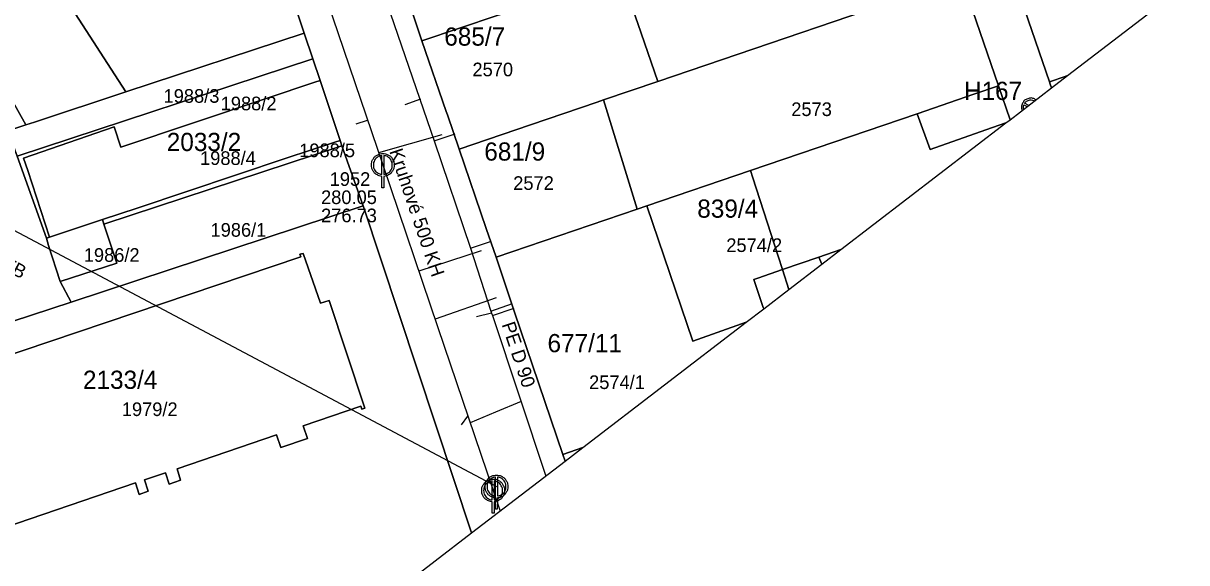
# Model space of a CAD drawing. Extents: x -570698 to -570232, y -1086952 to -1086596.
# Drawn here: x -570363.7 to -570235.9, y -1086825.7 to -1086766.4 of the extents above; entities that cross this region are included whole.
import ezdxf

# ---------------------------------------------------------------- set-up
doc = ezdxf.new("R2010")
doc.units = 0
for name, color, linetype in [('Adresní místo-text', 7, 'Continuous'), ('Default', 7, 'Continuous'), ('Hydrant', 7, 'Continuous'), ('Kanalizační přípojka', 7, 'Continuous'), ('Kanalizační stoka', 7, 'Continuous'), ('Kanalizační šachta', 7, 'Continuous'), ('Označení hydrantu', 7, 'Continuous'), ('Parcela-polygon', 7, 'Continuous'), ('Parcela-text', 7, 'Continuous'), ('Popis kmenové stoky', 7, 'Continuous'), ('Popis šachty', 7, 'Continuous'), ('Vodovodní přípojka', 7, 'Continuous'), ('Vodovodní řad', 7, 'Continuous'), ('Řad vodovodní popis', 7, 'Continuous')]:
    doc.layers.add(name, color=color, linetype=linetype)

msp = doc.modelspace()

# ---------------------------------------------------------------- linework, layer by layer
at = {"layer": 'Default'}
for points in [[(-570324.32, -1086783.21), (-570324.58, -1086783.19), (-570324.84, -1086783.04), (-570325.14, -1086782.88), (-570325.31, -1086782.58), (-570325.47, -1086782.28), (-570325.47, -1086781.96), (-570325.47, -1086781.63), (-570325.3, -1086781.33), (-570325.13, -1086781.03), (-570324.84, -1086780.87), (-570324.54, -1086780.71), (-570324.22, -1086780.71), (-570323.91, -1086780.71), (-570323.61, -1086780.87), (-570323.31, -1086781.03), (-570323.14, -1086781.33), (-570322.97, -1086781.63), (-570322.97, -1086781.96), (-570322.97, -1086782.28), (-570323.13, -1086782.58), (-570323.3, -1086782.88), (-570323.6, -1086783.04), (-570323.86, -1086783.19), (-570324.12, -1086783.21)], [(-570324.32, -1086780.92), (-570324.52, -1086780.94), (-570324.74, -1086781.05), (-570324.98, -1086781.19), (-570325.12, -1086781.44), (-570325.26, -1086781.69), (-570325.26, -1086781.96), (-570325.26, -1086782.23), (-570325.13, -1086782.48), (-570324.99, -1086782.72), (-570324.74, -1086782.86), (-570324.53, -1086782.98), (-570324.32, -1086783)], [(-570324.12, -1086783), (-570323.91, -1086782.98), (-570323.7, -1086782.86), (-570323.45, -1086782.72), (-570323.31, -1086782.48), (-570323.18, -1086782.23), (-570323.18, -1086781.96), (-570323.18, -1086781.69), (-570323.32, -1086781.44), (-570323.46, -1086781.19), (-570323.71, -1086781.05), (-570323.92, -1086780.94), (-570324.12, -1086780.92)], [(-570312.2, -1086819), (-570312.46, -1086818.98), (-570312.72, -1086818.83), (-570313.02, -1086818.67), (-570313.19, -1086818.37), (-570313.35, -1086818.07), (-570313.35, -1086817.75), (-570313.35, -1086817.42), (-570313.18, -1086817.12), (-570313.01, -1086816.82), (-570312.72, -1086816.66), (-570312.42, -1086816.5), (-570312.1, -1086816.5), (-570311.79, -1086816.5), (-570311.49, -1086816.66), (-570311.19, -1086816.82), (-570311.02, -1086817.12), (-570310.85, -1086817.42), (-570310.85, -1086817.75), (-570310.85, -1086818.07), (-570311.01, -1086818.37), (-570311.18, -1086818.67), (-570311.48, -1086818.83), (-570311.74, -1086818.98), (-570312, -1086819)], [(-570311.84, -1086818.57), (-570312.1, -1086818.55), (-570312.36, -1086818.4), (-570312.65, -1086818.24), (-570312.82, -1086817.94), (-570312.98, -1086817.64), (-570312.98, -1086817.32), (-570312.98, -1086816.99), (-570312.81, -1086816.69), (-570312.64, -1086816.39), (-570312.34, -1086816.23), (-570312.04, -1086816.07), (-570311.72, -1086816.07), (-570311.41, -1086816.07), (-570311.11, -1086816.23), (-570310.81, -1086816.4), (-570310.65, -1086816.7), (-570310.48, -1086817), (-570310.48, -1086817.33), (-570310.48, -1086817.65), (-570310.65, -1086817.95), (-570310.81, -1086818.24), (-570311.11, -1086818.41), (-570311.37, -1086818.55), (-570311.63, -1086818.57)], [(-570311.83, -1086816.28), (-570312.03, -1086816.3), (-570312.24, -1086816.41), (-570312.49, -1086816.55), (-570312.63, -1086816.8), (-570312.77, -1086817.05), (-570312.77, -1086817.32), (-570312.77, -1086817.59), (-570312.64, -1086817.83), (-570312.5, -1086818.08), (-570312.25, -1086818.22), (-570312.04, -1086818.34), (-570311.84, -1086818.36)], [(-570311.63, -1086818.36), (-570311.43, -1086818.34), (-570311.21, -1086818.22), (-570310.96, -1086818.09), (-570310.83, -1086817.84), (-570310.69, -1086817.6), (-570310.69, -1086817.33), (-570310.69, -1086817.05), (-570310.82, -1086816.8), (-570310.96, -1086816.55), (-570311.21, -1086816.42), (-570311.42, -1086816.3), (-570311.62, -1086816.28)], [(-570312.2, -1086816.71), (-570312.4, -1086816.73), (-570312.62, -1086816.84), (-570312.86, -1086816.98), (-570313, -1086817.23), (-570313.14, -1086817.48), (-570313.14, -1086817.75), (-570313.14, -1086818.02), (-570313.01, -1086818.27), (-570312.87, -1086818.51), (-570312.62, -1086818.65), (-570312.41, -1086818.77), (-570312.2, -1086818.79)], [(-570312, -1086818.79), (-570311.79, -1086818.77), (-570311.58, -1086818.65), (-570311.33, -1086818.51), (-570311.19, -1086818.27), (-570311.06, -1086818.02), (-570311.06, -1086817.75), (-570311.06, -1086817.48), (-570311.2, -1086817.23), (-570311.34, -1086816.98), (-570311.59, -1086816.84), (-570311.8, -1086816.73), (-570312, -1086816.71)]]:
    msp.add_open_spline(points, degree=3, dxfattribs=at)
at = {"layer": 'Hydrant'}
for p, q in [((-570253.77, -1086775.35), (-570253.39, -1086775.53)), ((-570253.23, -1086775.41), (-570253.69, -1086775.18)), ((-570253.39, -1086775.53), (-570253.23, -1086775.41)), ((-570252.59, -1086774.92), (-570252.43, -1086774.79)), ((-570253.94, -1086775.96), (-570253.78, -1086775.83))]:
    msp.add_line(p, q, dxfattribs=at)
for points, degree in [([(-570252.43, -1086774.79), (-570252.49, -1086774.75), (-570252.57, -1086774.72), (-570252.94, -1086774.54), (-570253.33, -1086774.68), (-570253.72, -1086774.81), (-570253.9, -1086775.18), (-570254.08, -1086775.56), (-570253.95, -1086775.95), (-570253.94, -1086775.95), (-570253.94, -1086775.96)], 3), ([(-570253.78, -1086775.83), (-570253.85, -1086775.59), (-570253.77, -1086775.35)], 2), ([(-570253.69, -1086775.18), (-570253.54, -1086774.95), (-570253.27, -1086774.85), (-570252.95, -1086774.74), (-570252.64, -1086774.89), (-570252.62, -1086774.9), (-570252.59, -1086774.92)], 3)]:
    msp.add_open_spline(points, degree=degree, dxfattribs=at)
at = {"layer": 'Kanalizační přípojka'}
for points in [[(-570327.16, -1086777.45), (-570325.89, -1086777.04)], [(-570317.74, -1086778.63), (-570324.68, -1086780.62)], [(-570313.43, -1086791.39), (-570320.26, -1086793.65)], [(-570311.78, -1086796.56), (-570318.48, -1086798.9)], [(-570309.02, -1086807.97), (-570311.82, -1086809.14), (-570314.62, -1086810.32)], [(-570315.57, -1086810.52), (-570314.86, -1086809.6)]]:
    msp.add_lwpolyline(points, dxfattribs=at)
at = {"layer": 'Kanalizační stoka'}
msp.add_line((-570387.02, -1086777.34), (-570311.73, -1086817.32), dxfattribs=at)
for points in [[(-570339.23, -1086738.28), (-570338.99, -1086738.49), (-570331.6, -1086760.23), (-570324.22, -1086781.96)], [(-570324.22, -1086781.96), (-570318.16, -1086799.85), (-570312.1, -1086817.75)], [(-570312.1, -1086817.75), (-570311.33, -1086820.02)]]:
    msp.add_lwpolyline(points, dxfattribs=at)
at = {"layer": 'Kanalizační šachta'}
for points in [[(-570324.32, -1086783), (-570324.32, -1086780.92)], [(-570324.12, -1086780.92), (-570324.12, -1086783)], [(-570324.12, -1086783.21), (-570324.12, -1086784.46), (-570324.32, -1086784.46), (-570324.32, -1086783.21)], [(-570311.84, -1086818.36), (-570311.83, -1086816.28)], [(-570311.62, -1086816.28), (-570311.63, -1086818.36)], [(-570312.2, -1086818.79), (-570312.2, -1086816.71)], [(-570312, -1086816.71), (-570312, -1086818.79)], [(-570312, -1086819), (-570312, -1086820.25), (-570312.2, -1086820.25), (-570312.2, -1086819)], [(-570311.63, -1086818.57), (-570311.64, -1086819.82), (-570311.84, -1086819.82), (-570311.84, -1086818.57)]]:
    msp.add_lwpolyline(points, dxfattribs=at)
at = {"layer": 'Parcela-polygon'}
for p, q in [((-570248.97, -1086772.14), (-570235.86, -1086762.07)), ((-570250.72, -1086773.48), (-570248.97, -1086772.14)), ((-570255.28, -1086776.98), (-570250.72, -1086773.48)), ((-570273.89, -1086791.27), (-570255.74, -1086777.34)), ((-570255.74, -1086777.34), (-570255.28, -1086776.98)), ((-570275.98, -1086792.88), (-570273.89, -1086791.27)), ((-570279.58, -1086795.64), (-570275.98, -1086792.88)), ((-570282.35, -1086797.77), (-570279.58, -1086795.64)), ((-570284.29, -1086799.25), (-570282.35, -1086797.77)), ((-570302.24, -1086813.03), (-570284.29, -1086799.25)), ((-570304.18, -1086814.52), (-570302.24, -1086813.03)), ((-570314.47, -1086822.42), (-570304.18, -1086814.52)), ((-570427.79, -1086909.43), (-570314.47, -1086822.42))]:
    msp.add_line(p, q, dxfattribs=at)
for points in [[(-570250.72, -1086773.48), (-570250.86, -1086773.06), (-570250.95, -1086772.82), (-570253.65, -1086764.94), (-570267.22, -1086725.38), (-570267.25, -1086723.7), (-570266.64, -1086718.69), (-570284.42, -1086711.51), (-570289.55, -1086724.3), (-570275.18, -1086729.09), (-570271.35, -1086730.46), (-570268.66, -1086737.98), (-570264.62, -1086749.76), (-570260.63, -1086761.38), (-570256.55, -1086773.27), (-570255.28, -1086776.98)], [(-570338.47, -1086750.66), (-570332.86, -1086767.46), (-570331.91, -1086770.3), (-570331.11, -1086772.68), (-570328.92, -1086779.26), (-570328.72, -1086779.86), (-570326.4, -1086786.46), (-570314.47, -1086822.42)], [(-570304.18, -1086814.52), (-570304.43, -1086813.78), (-570309.74, -1086798.14), (-570311.76, -1086792.1), (-570312.86, -1086788.94), (-570315.83, -1086780.22), (-570317.13, -1086776.46), (-570317.27, -1086776.07), (-570319.93, -1086768.31), (-570322.84, -1086759.63)], [(-570235.86, -1086762.07), (-570240.33, -1086763.5), (-570241.14, -1086760.94), (-570252.23, -1086764.49), (-570253.65, -1086764.94), (-570250.95, -1086772.82), (-570249.24, -1086772.23), (-570248.97, -1086772.14)], [(-570248.97, -1086772.14), (-570249.24, -1086772.23), (-570250.95, -1086772.82), (-570250.86, -1086773.06), (-570250.72, -1086773.48)], [(-570255.28, -1086776.98), (-570256.55, -1086773.27), (-570259.26, -1086774.19), (-570265.5, -1086776.32), (-570264.05, -1086780.26), (-570257.95, -1086778.09), (-570255.74, -1086777.34)], [(-570255.74, -1086777.34), (-570257.95, -1086778.09), (-570264.05, -1086780.26), (-570265.5, -1086776.32), (-570283.82, -1086782.57), (-570283.56, -1086783.38), (-570280.76, -1086792), (-570280.29, -1086793.46), (-570276.29, -1086792.09), (-570273.89, -1086791.27)], [(-570282.35, -1086797.77), (-570282.4, -1086797.62), (-570283.46, -1086794.55), (-570283.02, -1086794.4), (-570280.29, -1086793.46), (-570280.76, -1086792), (-570283.56, -1086783.38), (-570283.82, -1086782.57), (-570295.2, -1086786.45), (-570290.13, -1086801.35), (-570284.29, -1086799.25)], [(-570314.47, -1086822.42), (-570326.4, -1086786.46), (-570358.49, -1086797.03), (-570369.36, -1086800.59), (-570374.8, -1086803.82), (-570380.97, -1086807.48), (-570374.82, -1086826.12), (-570380.47, -1086828.04), (-570398.24, -1086834.1), (-570397.51, -1086836.02), (-570406.58, -1086839.09), (-570441.99, -1086865.7), (-570438.81, -1086873.31), (-570432.93, -1086886.42), (-570435.2, -1086888.38), (-570429.44, -1086901.1), (-570427.79, -1086909.43)], [(-570284.29, -1086799.25), (-570290.13, -1086801.35), (-570295.2, -1086786.45), (-570296.28, -1086786.82), (-570311.76, -1086792.1), (-570309.74, -1086798.14), (-570304.43, -1086813.78), (-570302.24, -1086813.03)], [(-570371.72, -1086823.85), (-570351.41, -1086816.93), (-570351, -1086818.18), (-570350, -1086817.84), (-570350.4, -1086816.58), (-570348.11, -1086815.81), (-570347.72, -1086817.05), (-570346.45, -1086816.63), (-570346.84, -1086815.37), (-570335.92, -1086811.65), (-570335.44, -1086813.04), (-570332.51, -1086812.04), (-570332.98, -1086810.65), (-570326.64, -1086808.49), (-570326.53, -1086808.82), (-570326.2, -1086808.71), (-570326.27, -1086808.48), (-570330.13, -1086796.86), (-570331.08, -1086797.16), (-570332.96, -1086791.7), (-570333.35, -1086791.78), (-570333.24, -1086792.07), (-570376.07, -1086806.51)], [(-570376.07, -1086806.51), (-570333.24, -1086792.07), (-570333.35, -1086791.78), (-570332.96, -1086791.7), (-570331.08, -1086797.16), (-570330.13, -1086796.86), (-570326.27, -1086808.48), (-570326.2, -1086808.71), (-570326.53, -1086808.82), (-570326.64, -1086808.49), (-570332.98, -1086810.65), (-570332.51, -1086812.04), (-570335.44, -1086813.04), (-570335.92, -1086811.65), (-570346.84, -1086815.37), (-570346.45, -1086816.63), (-570347.72, -1086817.05), (-570348.11, -1086815.81), (-570350.4, -1086816.58), (-570350, -1086817.84), (-570351, -1086818.18), (-570351.41, -1086816.93), (-570371.72, -1086823.85)], [(-570275.98, -1086792.88), (-570276.29, -1086792.09), (-570280.29, -1086793.46), (-570279.58, -1086795.64)], [(-570273.89, -1086791.27), (-570276.29, -1086792.09), (-570275.98, -1086792.88)], [(-570279.58, -1086795.64), (-570280.29, -1086793.46), (-570283.02, -1086794.4), (-570283.46, -1086794.55), (-570282.4, -1086797.62), (-570282.35, -1086797.77)], [(-570302.24, -1086813.03), (-570304.43, -1086813.78), (-570304.18, -1086814.52)]]:
    msp.add_lwpolyline(points, dxfattribs=at)
for points in [[(-570374.88, -1086758.41), (-570371.5, -1086763.53), (-570369.78, -1086766.25), (-570363.46, -1086777.55), (-570362.52, -1086777.24), (-570352.48, -1086773.93), (-570358.84, -1086764.07), (-570353.12, -1086760.09), (-570349.53, -1086757.78), (-570348.68, -1086757.23), (-570338.47, -1086750.66), (-570341.95, -1086740.28), (-570345.11, -1086739.23), (-570360.33, -1086749.01), (-570372.92, -1086757.22), (-570374.67, -1086758.28)], [(-570260.63, -1086761.38), (-570264.62, -1086749.76), (-570298.08, -1086760.98), (-570296.2, -1086766.41), (-570294, -1086772.77)], [(-570358.84, -1086764.07), (-570352.48, -1086773.93), (-570332.86, -1086767.46), (-570338.47, -1086750.66), (-570348.68, -1086757.23), (-570349.53, -1086757.78), (-570353.12, -1086760.09)], [(-570303.99, -1086762.89), (-570305.56, -1086758.39), (-570309.51, -1086759.74), (-570312.02, -1086752.49), (-570314.62, -1086753.37), (-570315.45, -1086753.64), (-570321.56, -1086755.69), (-570323.9, -1086756.47), (-570322.84, -1086759.63), (-570319.93, -1086768.31), (-570311.67, -1086765.54), (-570311.03, -1086765.33)], [(-570358.49, -1086797.03), (-570359.7, -1086794.79), (-570360.95, -1086790.81), (-570361.2, -1086790.01), (-570364.41, -1086781.01), (-570365.42, -1086778.19), (-570363.46, -1086777.55), (-570369.78, -1086766.25), (-570371.5, -1086763.53), (-570374.88, -1086758.41), (-570376.06, -1086759.12), (-570384.41, -1086764.61), (-570390.48, -1086768.31), (-570369.36, -1086800.59)], [(-570315.83, -1086780.22), (-570308, -1086777.55), (-570300.68, -1086775.05), (-570299.95, -1086774.8), (-570294, -1086772.77), (-570296.2, -1086766.41), (-570298.08, -1086760.98), (-570302.3, -1086762.3), (-570303.99, -1086762.89), (-570311.03, -1086765.33), (-570311.67, -1086765.54), (-570319.93, -1086768.31), (-570317.27, -1086776.07), (-570317.13, -1086776.46)], [(-570256.55, -1086773.27), (-570260.63, -1086761.38), (-570294, -1086772.77), (-570299.95, -1086774.8), (-570296.28, -1086786.82), (-570295.2, -1086786.45), (-570283.82, -1086782.57), (-570265.5, -1086776.32), (-570259.26, -1086774.19)], [(-570362.52, -1086777.24), (-570363.46, -1086777.55), (-570365.42, -1086778.19), (-570364.41, -1086781.01), (-570331.91, -1086770.3), (-570332.86, -1086767.46), (-570352.48, -1086773.93)], [(-570331.91, -1086770.3), (-570364.41, -1086781.01), (-570361.2, -1086790.01), (-570360.86, -1086789.89), (-570363.24, -1086782.57), (-570363.72, -1086781.21), (-570353.74, -1086777.77), (-570353.01, -1086780), (-570337.03, -1086774.66), (-570331.69, -1086772.87), (-570331.11, -1086772.68)], [(-570331.11, -1086772.68), (-570331.69, -1086772.87), (-570337.03, -1086774.66), (-570353.01, -1086780), (-570353.74, -1086777.77), (-570363.72, -1086781.21), (-570363.24, -1086782.57), (-570360.86, -1086789.89), (-570355.04, -1086787.97), (-570351.24, -1086786.71), (-570334.84, -1086781.23), (-570329.51, -1086779.46), (-570328.92, -1086779.26)], [(-570296.28, -1086786.82), (-570299.95, -1086774.8), (-570300.68, -1086775.05), (-570308, -1086777.55), (-570315.83, -1086780.22), (-570312.86, -1086788.94), (-570311.76, -1086792.1)], [(-570351.24, -1086786.71), (-570355.04, -1086787.97), (-570354.87, -1086788.47), (-570328.72, -1086779.86), (-570328.92, -1086779.26), (-570329.51, -1086779.46), (-570334.84, -1086781.23)], [(-570326.4, -1086786.46), (-570328.72, -1086779.86), (-570354.87, -1086788.47), (-570353.47, -1086792.75), (-570359.7, -1086794.79), (-570358.49, -1086797.03)], [(-570360.86, -1086789.89), (-570361.2, -1086790.01), (-570360.95, -1086790.81), (-570359.7, -1086794.79), (-570353.47, -1086792.75), (-570354.87, -1086788.47), (-570355.04, -1086787.97)]]:
    msp.add_lwpolyline(points, close=True, dxfattribs=at)
at = {"layer": 'Vodovodní přípojka'}
for p, q in [((-570320.09, -1086774.71), (-570321.82, -1086775.34)), ((-570318.59, -1086779.29), (-570316.26, -1086778.53)), ((-570314.6, -1086791.1), (-570312.26, -1086790.35)), ((-570312.35, -1086798.02), (-570309.96, -1086797.21)), ((-570312.26, -1086798.25), (-570313.91, -1086798.67)), ((-570312.16, -1086798.51), (-570309.77, -1086797.7))]:
    msp.add_line(p, q, dxfattribs=at)
at = {"layer": 'Vodovodní řad'}
msp.add_lwpolyline([(-570335.76, -1086729.44), (-570333.92, -1086733.97), (-570328.72, -1086749.21), (-570327.41, -1086753.09), (-570324.57, -1086761.8), (-570318.59, -1086779.29), (-570314.6, -1086791.1), (-570312.35, -1086798.02), (-570312.26, -1086798.25), (-570312.16, -1086798.51), (-570306.32, -1086816.17)], dxfattribs=at)

# ---------------------------------------------------------------- texts
at = {"layer": 'Adresní místo-text'}
for s, p in [('685/7', (-570317.47, -1086768.84)), ('2033/2', (-570347.97, -1086780.43)), ('681/9', (-570313.07, -1086781.48)), ('839/4', (-570289.66, -1086787.76)), ('677/11', (-570306.12, -1086802.55)), ('2133/4', (-570357.18, -1086806.58))]:
    msp.add_text(s, height=2, dxfattribs=at).set_placement(p)
at = {"layer": 'Označení hydrantu'}
msp.add_text('H167', height=2, dxfattribs=at).set_placement((-570260.35, -1086774.81))
at = {"layer": 'Parcela-text'}
for s, p in [('2570', (-570314.37, -1086772.21)), ('1988/3', (-570348.32, -1086775.12)), ('1988/2', (-570342.04, -1086775.95)), ('2573', (-570279.33, -1086776.58)), ('1988/4', (-570344.31, -1086781.96)), ('1988/5', (-570333.41, -1086781.1)), ('2572', (-570309.89, -1086784.7)), ('1986/1', (-570343.16, -1086789.85)), ('2574/2', (-570286.47, -1086791.53)), ('1986/2', (-570357.09, -1086792.61)), ('2574/1', (-570301.55, -1086806.6)), ('1979/2', (-570352.91, -1086809.57))]:
    msp.add_text(s, height=1.5, dxfattribs=at).set_placement(p)
at = {"layer": 'Popis kmenové stoky'}
for s, rotation, p in [('Kruhové 500 KH', 288.7083, (-570323.53, -1086780.45)), ('Kruhové 500 TB', 332.0311, (-570376.73, -1086787.74))]:
    msp.add_text(s, height=1.5, rotation=rotation, dxfattribs=at).set_placement(p)
at = {"layer": 'Popis šachty'}
for s, p in [('1952', (-570330.06, -1086784.26)), ('280.05', (-570331.01, -1086786.26)), ('276.73', (-570331.01, -1086788.26))]:
    msp.add_text(s, height=1.5, dxfattribs=at).set_placement(p)
at = {"layer": 'Řad vodovodní popis'}
msp.add_text('PE D 90', height=1.5, rotation=288.3103, dxfattribs=at).set_placement((-570311.18, -1086799.49))

doc.saveas('drawing.dxf')
